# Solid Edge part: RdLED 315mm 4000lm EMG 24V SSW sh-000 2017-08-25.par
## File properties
Author: lukasz.lemanski
Template: iso metric part.par
Last saved by: lukasz.lemanski
Revision: 1
Application: Solid Edge
Username: lukasz.lemanski
Gęstość: 0,000 kg/m^3
Dokładność: 0,990
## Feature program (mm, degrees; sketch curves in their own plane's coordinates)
body "unnamed Body 1"
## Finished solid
Body 1: solid body, 3086 faces, 7992 edges, 5202 vertices, 3 separate solids.
  Faces by surface: plane 2559, cylinder 241, spline 160, cone 52, torus 22, sphere 20, swept 18, spun 14
  Edges by curve: line 6852, curve on surface 600, circle 320, ellipse 132, spline 76, intersection 12
Bounding box of the edges (mm; curved faces can reach further): 311.800 x 4.500 x 311.800, from (-155.9, -3.5, -155.9) to (155.9, 1, 155.9).
Cylindrical faces by radius (mm): R0.2 x78, R0.2002 x4, R0.2169 x6, R0.25 x24, R0.3 x4, R0.3373 x6, R0.4 x16, R0.4006 x4, R0.4008 x4, R0.525 x4, R0.6 x24, R0.75 x9, R1 x14, R1.0894 x4, R1.1 x28, R2.15 x8, R157.5 x4
Conical faces (half-angle, radius in mm at the cone's reference point): 0.5 deg R0.5056 x8, 0.5 deg R1.0082 x8, 1 deg R0.5511 x4, 10 deg R0.2132 x4, 10 deg R0.4132 x4, 18.4844 deg R1.0657 x8, 27.363 deg R0.6214 x4, 45 deg R0.575 x4, 45 deg R0.625 x8
Toroidal faces (ring radius, tube radius in mm): R0.1 r0.2 x2, R0.8 r0.2 x8, R0.8522 r0.3 x4, R0.9002 r0.2 x2, R0.9018 r0.2 x2, R1.3 r0.2 x4
Spherical faces by radius (mm): R0.2 x16, R0.6 x4
Planar faces by outward normal: +x 61, +y 23, +z 61, -x 61, -y 460, -z 81, oblique 1812
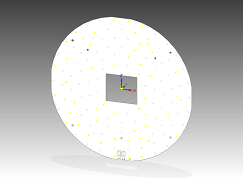
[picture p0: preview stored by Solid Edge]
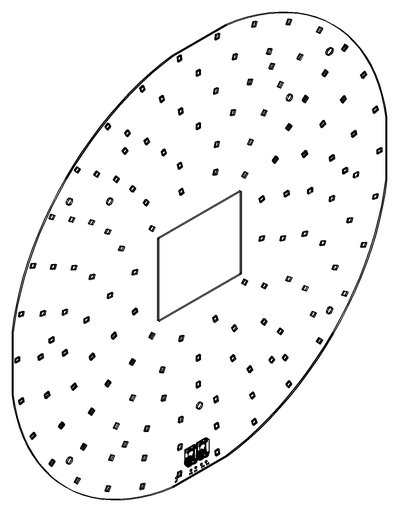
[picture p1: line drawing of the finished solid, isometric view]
